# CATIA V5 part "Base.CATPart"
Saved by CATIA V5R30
Part number: Part1
Bounding box of the stored display mesh (mm): x -50 to 50, y -25 to 25, z 0 to 50
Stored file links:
  D:\PROJECTS\CATIA V56R 2020\Resources\Parts File\c12_catia_v5_6r2020_prt\c12_catia_v5-6r2020 figr_12-22\Base.CATPart
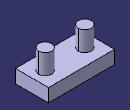
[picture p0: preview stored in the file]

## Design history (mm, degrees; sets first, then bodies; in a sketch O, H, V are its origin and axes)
Body1 (main body)
  Sketch1 on xy-plane, origin (0, 0, 0), H (1, 0, 0), V (0, 1, 0)
    line L1 (50, 25) -> (50, -25)
    line L2 (50, -25) -> (-50, -25)
    line L3 (-50, -25) -> (-50, 25)
    line L4 (-50, 25) -> (50, 25)
    circle A1 centre (-30, 0) radius 10
    point P5 (-30, 0)
    circle A2 centre (30, 0) radius 10
    length L2 = 100
    length L1 = 50
    radius A1 = 10
    distance P5 V = 30
    vertical: L1 V, L3 V
    horizontal: L2 H, L4 H
    equidistance: L1 L3 O, L2 L4 O
    coincidence: P5 H
    symmetry: A1 A2 V
  MultiPad1: profile Sketch1, domains (length 20; length 50; length 50)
